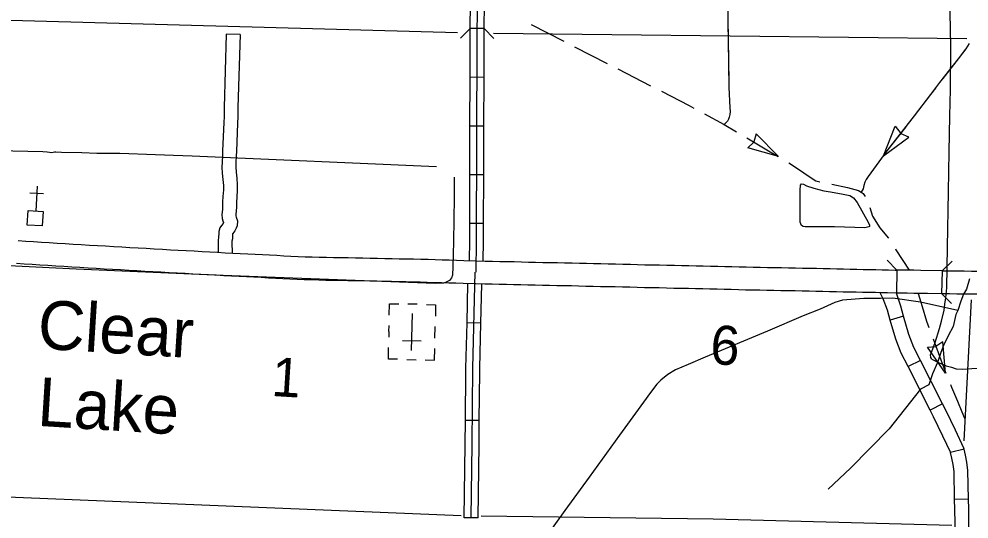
# Model space of a CAD drawing. Extents: x 1366406 to 1373462, y 376856 to 381998.
# Drawn here: x 1369358.5 to 1369525.2, y 379511.9 to 379599.7 of the extents above; entities that cross this region are included whole.
import ezdxf

# ---------------------------------------------------------------- set-up
doc = ezdxf.new("R2010")
doc.units = 0
for name, color, linetype in [('10', 7, 'Continuous'), ('24', 7, 'Continuous'), ('31', 7, 'Continuous'), ('32', 7, 'Continuous'), ('35', 7, 'Continuous'), ('37', 7, 'Continuous'), ('38', 7, 'Continuous'), ('4', 7, 'Continuous'), ('43', 7, 'Continuous'), ('45', 7, 'Continuous'), ('46', 7, 'Continuous'), ('5', 7, 'Continuous'), ('57', 7, 'Continuous')]:
    doc.layers.add(name, color=color, linetype=linetype)

msp = doc.modelspace()

# ---------------------------------------------------------------- linework, layer by layer
at = {"layer": '10'}
msp.add_line((1369520.56, 379555.48), (1369520.53, 379555.48), dxfattribs=at)
for points in [[(1369358.35, 379560.78), (1369359.71, 379560.69), (1369361.07, 379560.6), (1369362.44, 379560.52), (1369363.82, 379560.44), (1369365.22, 379560.35), (1369366.63, 379560.26), (1369368.03, 379560.17), (1369369.45, 379560.08), (1369370.86, 379560), (1369372.28, 379559.92), (1369373.71, 379559.84), (1369375.15, 379559.75), (1369376.57, 379559.66), (1369377.99, 379559.58), (1369379.4, 379559.5), (1369380.82, 379559.43), (1369382.25, 379559.35), (1369383.67, 379559.26), (1369385.08, 379559.18), (1369386.47, 379559.1), (1369387.86, 379559.02), (1369389.25, 379558.95), (1369390.63, 379558.88), (1369391.99, 379558.8), (1369393.37, 379558.73), (1369394.7, 379558.65), (1369396.02, 379558.57), (1369397.33, 379558.51), (1369398.64, 379558.45), (1369399.94, 379558.39), (1369401.22, 379558.32), (1369402.49, 379558.26), (1369403.76, 379558.19), (1369405.01, 379558.13), (1369406.24, 379558.07), (1369407.51, 379558.01), (1369408.72, 379557.95), (1369409.96, 379557.91)], [(1369409.82, 379553.86), (1369408.55, 379553.9), (1369407.31, 379553.96), (1369406.05, 379554.03), (1369404.81, 379554.09), (1369403.56, 379554.15), (1369402.29, 379554.21), (1369401.01, 379554.28), (1369399.74, 379554.34), (1369398.45, 379554.4), (1369397.14, 379554.46), (1369395.81, 379554.53), (1369394.46, 379554.6), (1369393.14, 379554.69), (1369391.78, 379554.76), (1369390.41, 379554.83), (1369389.04, 379554.91), (1369387.65, 379554.98), (1369386.25, 379555.05), (1369384.84, 379555.13), (1369383.43, 379555.22), (1369382.02, 379555.31), (1369380.61, 379555.38), (1369379.19, 379555.46), (1369377.76, 379555.53), (1369376.33, 379555.62), (1369374.9, 379555.71), (1369373.47, 379555.79), (1369372.05, 379555.88), (1369370.63, 379555.96), (1369369.21, 379556.04), (1369367.78, 379556.13), (1369366.37, 379556.22), (1369364.96, 379556.31), (1369363.57, 379556.39), (1369362.19, 379556.48), (1369360.81, 379556.56), (1369359.44, 379556.65), (1369358.08, 379556.74)], [(1369409.95, 379557.91), (1369411.21, 379557.87), (1369412.46, 379557.84), (1369413.72, 379557.82), (1369414.99, 379557.8), (1369416.27, 379557.78), (1369417.56, 379557.76), (1369418.85, 379557.74), (1369420.14, 379557.71), (1369421.42, 379557.68), (1369422.7, 379557.65), (1369423.97, 379557.63), (1369425.24, 379557.6), (1369426.5, 379557.58), (1369427.76, 379557.55), (1369429.02, 379557.52), (1369430.29, 379557.49), (1369431.55, 379557.44), (1369432.78, 379557.4), (1369434.02, 379557.37), (1369435.29, 379557.34), (1369436.57, 379557.31), (1369438.63, 379557.24), (1369438.79, 379557.24), (1369440.34, 379557.19), (1369441.61, 379557.17), (1369442.88, 379557.13), (1369444.14, 379557.1), (1369445.4, 379557.08), (1369446.67, 379557.04), (1369447.94, 379557.01), (1369449.17, 379556.98), (1369450.45, 379556.96), (1369451.7, 379556.93), (1369452.98, 379556.91), (1369454.24, 379556.88), (1369455.57, 379556.87), (1369456.84, 379556.82), (1369458.08, 379556.79), (1369459.35, 379556.76), (1369460.64, 379556.74), (1369461.91, 379556.71), (1369463.21, 379556.68), (1369464.5, 379556.65), (1369465.79, 379556.62), (1369467.07, 379556.59), (1369468.34, 379556.55), (1369469.63, 379556.53), (1369470.93, 379556.51), (1369472.22, 379556.47), (1369473.51, 379556.44), (1369474.78, 379556.41), (1369476.05, 379556.39), (1369477.32, 379556.37), (1369478.59, 379556.34), (1369479.86, 379556.31), (1369481.12, 379556.28), (1369482.37, 379556.25), (1369483.62, 379556.22), (1369484.87, 379556.18), (1369486.11, 379556.15), (1369487.35, 379556.12), (1369488.59, 379556.1), (1369489.83, 379556.08), (1369491.07, 379556.06), (1369492.3, 379556.03), (1369493.54, 379556.01), (1369494.76, 379555.98), (1369495.99, 379555.96), (1369497.22, 379555.94), (1369498.44, 379555.91), (1369499.65, 379555.88), (1369500.84, 379555.85), (1369502.02, 379555.83), (1369503.19, 379555.8), (1369504.35, 379555.78), (1369505.51, 379555.75), (1369506.64, 379555.73), (1369507.75, 379555.7), (1369508.86, 379555.69), (1369509.96, 379555.66), (1369511.06, 379555.63), (1369512.25, 379555.59), (1369512.57, 379555.59)], [(1369512.57, 379555.59), (1369512.5, 379551.54), (1369510.94, 379551.58), (1369509.86, 379551.61), (1369508.78, 379551.64), (1369507.68, 379551.66), (1369506.55, 379551.68), (1369505.42, 379551.7), (1369504.27, 379551.73), (1369503.11, 379551.75), (1369501.94, 379551.78), (1369500.75, 379551.8), (1369499.55, 379551.83), (1369498.34, 379551.86), (1369497.14, 379551.89), (1369495.92, 379551.91), (1369494.69, 379551.94), (1369493.46, 379551.96), (1369492.22, 379551.98), (1369490.99, 379552.01), (1369489.75, 379552.03), (1369488.51, 379552.05), (1369487.27, 379552.08), (1369486.02, 379552.1), (1369484.76, 379552.14), (1369483.51, 379552.17), (1369482.27, 379552.2), (1369481.02, 379552.23), (1369479.76, 379552.26), (1369478.51, 379552.29), (1369477.25, 379552.32), (1369475.98, 379552.34), (1369474.7, 379552.36), (1369473.41, 379552.39), (1369472.13, 379552.43), (1369470.84, 379552.46), (1369469.55, 379552.48), (1369468.25, 379552.51), (1369466.96, 379552.54), (1369465.68, 379552.58), (1369464.4, 379552.61), (1369463.12, 379552.64), (1369461.82, 379552.66), (1369460.55, 379552.69), (1369459.28, 379552.71), (1369457.99, 379552.74), (1369456.7, 379552.77), (1369455.48, 379552.82), (1369454.18, 379552.83), (1369452.89, 379552.86), (1369451.62, 379552.88), (1369450.37, 379552.91), (1369449.1, 379552.93), (1369447.83, 379552.96), (1369446.57, 379552.99), (1369445.31, 379553.03), (1369444.04, 379553.06), (1369442.78, 379553.08), (1369441.53, 379553.12), (1369440.25, 379553.14), (1369438.66, 379553.19), (1369438.49, 379553.19), (1369436.45, 379553.26), (1369435.19, 379553.29), (1369433.94, 379553.32), (1369432.67, 379553.35), (1369431.4, 379553.39), (1369430.16, 379553.44), (1369428.92, 379553.47), (1369427.67, 379553.5), (1369426.42, 379553.53), (1369425.16, 379553.55), (1369423.89, 379553.58), (1369422.62, 379553.6), (1369421.33, 379553.63), (1369420.05, 379553.66), (1369418.77, 379553.69), (1369417.49, 379553.71), (1369416.21, 379553.74), (1369414.94, 379553.75), (1369413.65, 379553.77), (1369412.37, 379553.79), (1369411.1, 379553.82), (1369409.83, 379553.86)], [(1369520.56, 379555.48), (1369516.78, 379555.55), (1369515.56, 379555.57), (1369512.57, 379555.59)], [(1369533.29, 379551.28), (1369532, 379551.3), (1369530.73, 379551.32), (1369529.45, 379551.33), (1369528.18, 379551.35), (1369526.9, 379551.36), (1369525.61, 379551.37), (1369524.33, 379551.39), (1369523.06, 379551.4), (1369521.78, 379551.41), (1369520.49, 379551.43), (1369520.44, 379551.43), (1369520.56, 379555.48)], [(1369520.53, 379555.48), (1369520.56, 379555.48), (1369521.82, 379555.46), (1369523.09, 379555.45), (1369524.38, 379555.44), (1369525.66, 379555.42), (1369526.94, 379555.41), (1369528.22, 379555.4), (1369529.5, 379555.38), (1369530.79, 379555.37), (1369532.07, 379555.35), (1369533.35, 379555.33)], [(1369520.49, 379551.43), (1369517.95, 379551.48), (1369516.7, 379551.5), (1369515.51, 379551.52), (1369514.34, 379551.53), (1369512.5, 379551.54)]]:
    msp.add_lwpolyline(points, dxfattribs=at)
at = {"layer": '31'}
msp.add_lwpolyline([(1369518.7, 379539.94), (1369519.99, 379539.34), (1369521.22, 379538.81), (1369522.12, 379538.54), (1369522.97, 379538.26), (1369524.13, 379538.19), (1369525.72, 379538.32), (1369526.71, 379538.39), (1369527.68, 379538.45), (1369530.55, 379538.61), (1369534.4, 379538.6), (1369563.62, 379538.83), (1369564.22, 379538.94), (1369564.66, 379539.22), (1369564.83, 379539.54), (1369564.88, 379539.85), (1369564.96, 379543.36), (1369565.19, 379558.13), (1369565.46, 379598.16), (1369565.57, 379608.14), (1369565.83, 379631.95), (1369565.94, 379634.8), (1369566.02, 379636.5)], dxfattribs=at)
at = {"layer": '32'}
for p, q in [((1369440.14, 379597.97), (1369437.71, 379597.99)), ((1369440.11, 379589.42), (1369437.68, 379589.43)), ((1369440.08, 379580.87), (1369437.65, 379580.88)), ((1369440.06, 379572.31), (1369437.63, 379572.32)), ((1369440.03, 379563.76), (1369437.6, 379563.77)), ((1369513.73, 379547.52), (1369511.39, 379546.84)), ((1369516.68, 379539.76), (1369514.52, 379538.66)), ((1369520.57, 379532.14), (1369518.4, 379531.04)), ((1369524.35, 379524.15), (1369521.99, 379523.59)), ((1369525.12, 379515.41), (1369522.69, 379515.35))]:
    msp.add_line(p, q, dxfattribs=at)
for points in [[(1369438.72, 379555.21), (1369438.81, 379560.76), (1369438.91, 379595.76), (1369438.95, 379602.35), (1369438.99, 379604.79), (1369439.05, 379606.18), (1369439.14, 379607.55), (1369439.14, 379619.93), (1369439.06, 379625.24)], [(1369437.71, 379597.99), (1369437.74, 379602.37), (1369437.78, 379604.83), (1369437.84, 379606.25), (1369437.86, 379606.61)], [(1369440.14, 379597.97), (1369440.17, 379602.34), (1369440.2, 379604.76), (1369440.26, 379606.11), (1369440.29, 379606.45)], [(1369518.7, 379539.94), (1369518.51, 379540.26), (1369518.48, 379540.74), (1369518.7, 379541.32), (1369519.3, 379542.91), (1369520.05, 379545.34), (1369520.38, 379546.61), (1369520.87, 379548.55), (1369520.98, 379549.59), (1369521.16, 379550.73), (1369521.32, 379552.51), (1369521.42, 379559.65), (1369521.59, 379569.35), (1369521.76, 379576.33), (1369521.84, 379582.62), (1369521.98, 379587.3), (1369522.01, 379595.1), (1369521.97, 379597.66), (1369521.83, 379604.34)], [(1369437.68, 379589.43), (1369437.7, 379595.77), (1369437.71, 379597.99)], [(1369440.11, 379589.42), (1369440.13, 379595.76), (1369440.14, 379597.97)], [(1369437.65, 379580.88), (1369437.68, 379589.43)], [(1369440.08, 379580.87), (1369440.11, 379589.42)], [(1369437.63, 379572.32), (1369437.65, 379580.88)], [(1369440.06, 379572.31), (1369440.08, 379580.87)], [(1369437.6, 379563.77), (1369437.63, 379572.32)], [(1369440.03, 379563.76), (1369440.06, 379572.31)], [(1369437.54, 379557.28), (1369437.6, 379560.77), (1369437.6, 379563.77)], [(1369439.97, 379557.19), (1369440.03, 379560.75), (1369440.03, 379563.76)], [(1369511.39, 379546.84), (1369510.89, 379548.56), (1369510.18, 379550.58), (1369509.62, 379551.62)], [(1369513.73, 379547.52), (1369513.23, 379549.24), (1369512.5, 379551.54)], [(1369514.52, 379538.66), (1369513.32, 379541), (1369512.37, 379543.5), (1369511.39, 379546.84)], [(1369516.68, 379539.76), (1369515.55, 379541.99), (1369514.67, 379544.27), (1369513.73, 379547.52)], [(1369518.4, 379531.04), (1369514.52, 379538.66)], [(1369520.57, 379532.14), (1369516.68, 379539.76)], [(1369524.35, 379524.15), (1369524.31, 379524.35), (1369522.83, 379527.52), (1369521.18, 379530.92), (1369520.57, 379532.14)], [(1369522, 379523.55), (1369520.63, 379526.48), (1369519.01, 379529.85), (1369518.4, 379531.04)], [(1369522.69, 379515.35), (1369522.59, 379520.27), (1369522.43, 379521.5), (1369522.22, 379522.59), (1369521.99, 379523.59)], [(1369525.12, 379515.41), (1369525.01, 379520.45), (1369524.83, 379521.88), (1369524.6, 379523.1), (1369524.35, 379524.15)], [(1369522.75, 379506.83), (1369522.76, 379511.12), (1369522.73, 379513.66), (1369522.69, 379515.35)], [(1369525.18, 379506.82), (1369525.19, 379511.13), (1369525.16, 379513.71), (1369525.12, 379515.41)]]:
    msp.add_lwpolyline(points, dxfattribs=at)
at = {"layer": '35'}
for points in [[(1369501.62, 379563.17), (1369496.48, 379563.2), (1369496.09, 379563.26), (1369495.81, 379563.41), (1369495.58, 379564.01), (1369495.61, 379569.61), (1369495.63, 379570.53), (1369495.81, 379570.75), (1369496.16, 379570.69), (1369496.7, 379570.36), (1369497.99, 379569.96), (1369499.76, 379569.48), (1369500.9, 379569.35)], [(1369500.9, 379569.35), (1369503.13, 379568.94), (1369504.32, 379568.66), (1369504.96, 379568.25), (1369505.59, 379567.45), (1369507.5, 379563.98), (1369507.77, 379563.51), (1369507.75, 379563.25), (1369507.65, 379563.19), (1369506.92, 379563), (1369501.62, 379563.17)]]:
    msp.add_lwpolyline(points, dxfattribs=at)
at = {"layer": '37'}
for points in [[(1369510.88, 379557.34), (1369512.57, 379555.59)], [(1369520.54, 379555.51), (1369522.28, 379557.19)], [(1369512.5, 379551.54), (1369512.5, 379551.54)], [(1369522.16, 379549.71), (1369520.47, 379551.46)]]:
    msp.add_lwpolyline(points, dxfattribs=at)
at = {"layer": '38'}
for points in [[(1369435.98, 379596.28), (1369437.71, 379597.99)], [(1369440.14, 379597.97), (1369441.85, 379596.24)]]:
    msp.add_lwpolyline(points, dxfattribs=at)
at = {"layer": '4'}
for points in [[(1369435.47, 379597.25), (1369354.8, 379599.47), (1369353.11, 379599.52), (1369318.41, 379599.46), (1369311.47, 379599.63)], [(1369524.83, 379596.17), (1369441.79, 379597.12)]]:
    msp.add_lwpolyline(points, dxfattribs=at)
at = {"layer": '43'}
for p, q in [((1369510.2, 379575.67), (1369512.27, 379580.83)), ((1369512.27, 379580.83), (1369513.33, 379579.49)), ((1369487.87, 379579.5), (1369487.47, 379578.08)), ((1369491.76, 379575.52), (1369487.87, 379579.5)), ((1369510.2, 379575.67), (1369514.68, 379578.95)), ((1369514.68, 379578.95), (1369513.33, 379579.49)), ((1369486.41, 379577.03), (1369487.46, 379578.06)), ((1369491.76, 379575.52), (1369486.41, 379577.03)), ((1369517.91, 379542.05), (1369519.38, 379542.18)), ((1369521.1, 379537.5), (1369517.91, 379542.05)), ((1369520.61, 379543.03), (1369519.4, 379542.19)), ((1369521.1, 379537.5), (1369520.61, 379543.03))]:
    msp.add_line(p, q, dxfattribs=at)
for points in [[(1369482.56, 379624.5), (1369483.09, 379587.69), (1369483.23, 379584.06), (1369483.3, 379583.41), (1369483.23, 379582.92), (1369483.13, 379582.46), (1369483.03, 379582.1), (1369482.81, 379581.76), (1369482.24, 379581.17)], [(1369448.4, 379598.71), (1369451.26, 379597.25)], [(1369482.92, 379599.01), (1369483.02, 379592.6)], [(1369451.26, 379597.25), (1369454.11, 379595.78)], [(1369525.24, 379595.36), (1369524.65, 379594.44), (1369523.3, 379592.69), (1369520.05, 379588.51), (1369518.48, 379586.42), (1369515.6, 379582.65), (1369510.82, 379576.51), (1369507.5, 379572.05), (1369507.19, 379571.52), (1369506.91, 379571.01), (1369506.76, 379570.46), (1369506.62, 379569.88), (1369506.32, 379569.29)], [(1369456.01, 379594.8), (1369461.72, 379591.87)], [(1369524.55, 379594.31), (1369523.3, 379592.69), (1369520.61, 379589.24)], [(1369463.62, 379590.89), (1369469.32, 379587.96)], [(1369483.05, 379590.46), (1369483.09, 379587.69), (1369483.23, 379584.06), (1369483.23, 379584.05)], [(1369471.23, 379586.98), (1369476.13, 379584.46), (1369476.92, 379584.04)], [(1369519.32, 379587.54), (1369518.48, 379586.42), (1369515.6, 379582.65), (1369515.43, 379582.44)], [(1369478.81, 379583.02), (1369482.24, 379581.17), (1369484.4, 379579.89)], [(1369482.94, 379581.97), (1369482.81, 379581.76), (1369482.24, 379581.17)], [(1369514.12, 379580.75), (1369510.82, 379576.51), (1369510.2, 379575.67)], [(1369486.24, 379578.8), (1369490.32, 379576.37), (1369491.75, 379575.51)], [(1369431.8, 379573.71), (1369388.88, 379575.58), (1369385.6, 379575.68), (1369382.45, 379575.81), (1369376.21, 379576.06), (1369372.2, 379576.08), (1369369.56, 379576.16), (1369365.95, 379576.24), (1369364.98, 379576.32), (1369364.76, 379576.28), (1369364.25, 379576.19), (1369363.45, 379576.27), (1369362.71, 379576.35), (1369318.1, 379577.32)], [(1369493.58, 379574.4), (1369494.61, 379573.77), (1369496.26, 379572.64)], [(1369508.92, 379573.95), (1369507.5, 379572.05), (1369507.19, 379571.52), (1369506.91, 379571.01), (1369506.76, 379570.46), (1369506.62, 379569.88), (1369506.32, 379569.29)], [(1369434.9, 379571.88), (1369434.9, 379568.36), (1369434.74, 379560.59), (1369434.66, 379556.18), (1369434.58, 379554.72), (1369434.43, 379554.22), (1369434.06, 379553.75), (1369433.35, 379553.41), (1369432.98, 379553.28), (1369431.56, 379553.27), (1369403.46, 379554.28), (1369392.81, 379554.72), (1369368.55, 379555.77), (1369350.77, 379556.66), (1369342.6, 379557.05)], [(1369496.26, 379572.64), (1369497.68, 379571.66), (1369498.32, 379571.25), (1369499.03, 379571.1)], [(1369501.12, 379570.66), (1369503.91, 379570.07), (1369505.83, 379569.56), (1369506.32, 379569.29), (1369506.66, 379569.02), (1369506.97, 379568.53)], [(1369507.79, 379566.57), (1369508.3, 379565.05), (1369509.58, 379563.02), (1369511.08, 379561.23)], [(1369512.32, 379559.3), (1369512.4, 379559.13), (1369514.73, 379555.59)], [(1369525.29, 379554.09), (1369524.76, 379552.27), (1369524.27, 379551.4), (1369523.78, 379550.17), (1369523.24, 379548.49), (1369522.9, 379547.78), (1369522.41, 379545.72), (1369521.55, 379544.08), (1369520.73, 379542.39), (1369520.29, 379541.11), (1369519.67, 379539.38), (1369518.79, 379537.4), (1369518.19, 379535.47), (1369516.73, 379534.68), (1369511.19, 379527.74), (1369504.42, 379520.86), (1369500.49, 379517.18)], [(1369516.3, 379551.5), (1369516.99, 379549.21), (1369517.76, 379546.64), (1369518.17, 379545.53)], [(1369523.24, 379548.49), (1369516.72, 379549.98), (1369511.84, 379550.67), (1369509.69, 379550.61), (1369506.74, 379550.64), (1369503.03, 379550.32), (1369501.69, 379549.92), (1369499.12, 379548.77), (1369496.1, 379547.55), (1369489.87, 379544.86), (1369478.9, 379540.31), (1369475.95, 379539.06), (1369473.71, 379538.11), (1369472.34, 379537.25), (1369471.13, 379536.31), (1369470.46, 379535.57), (1369469.31, 379534.11), (1369468.07, 379532.4), (1369463.89, 379526.63), (1369458.54, 379519.24), (1369454.31, 379513.44), (1369451.03, 379508.82)], [(1369518.9, 379543.52), (1369520.25, 379539.83), (1369521.17, 379537.52)], [(1369521.95, 379535.53), (1369522.14, 379535.05), (1369523.18, 379532.57)], [(1369523.18, 379532.57), (1369523.95, 379530.75), (1369524.42, 379529.61)]]:
    msp.add_lwpolyline(points, dxfattribs=at)
at = {"layer": '45'}
for p, q in [((1369439.57, 379546.29), (1369437.14, 379546.35)), ((1369439.29, 379529.21), (1369436.86, 379529.23)), ((1369439.06, 379512.1), (1369436.63, 379512.13))]:
    msp.add_line(p, q, dxfattribs=at)
for points in [[(1369437.85, 379512.11), (1369438.03, 379525.06), (1369438.17, 379538.39), (1369438.56, 379555.22)], [(1369437.14, 379546.35), (1369437.3, 379553.23)], [(1369439.57, 379546.29), (1369439.73, 379553.15)], [(1369436.95, 379537.78), (1369436.95, 379538.41), (1369437.14, 379546.35)], [(1369439.38, 379537.76), (1369439.38, 379538.37), (1369439.57, 379546.29)], [(1369436.86, 379529.23), (1369436.95, 379537.78)], [(1369439.29, 379529.21), (1369439.38, 379537.76)], [(1369436.75, 379520.68), (1369436.81, 379525.07), (1369436.86, 379529.23)], [(1369439.18, 379520.65), (1369439.24, 379525.04), (1369439.29, 379529.21)], [(1369436.63, 379512.13), (1369436.75, 379520.68)], [(1369439.06, 379512.1), (1369439.18, 379520.65)]]:
    msp.add_lwpolyline(points, dxfattribs=at)
at = {"layer": '46'}
for points in [[(1369397.3, 379596.94), (1369394.88, 379597.01), (1369394.49, 379584.16), (1369394.49, 379582.53), (1369394.46, 379581.47), (1369394.24, 379576.54), (1369394.2, 379575.79), (1369394.14, 379574.56), (1369394.13, 379573.64), (1369394.17, 379572.58), (1369394.29, 379571.52), (1369394.37, 379570.46), (1369394.37, 379569.68), (1369394.3, 379568.54), (1369394.25, 379567.57), (1369394.25, 379566.82), (1369394.2, 379566.22), (1369394.09, 379565.37), (1369394.19, 379564.66), (1369394.31, 379564.23), (1369394.39, 379563.93), (1369394.39, 379563.93), (1369394.32, 379563.79), (1369394.06, 379563.44), (1369393.74, 379562.99), (1369393.58, 379562.37), (1369393.58, 379562.17), (1369393.56, 379561.99), (1369393.52, 379561.42), (1369393.52, 379561.28), (1369393.45, 379560.89), (1369393.45, 379558.72)], [(1369397.3, 379596.94), (1369396.92, 379584.12), (1369396.92, 379582.49), (1369396.88, 379581.38), (1369396.67, 379576.41), (1369396.62, 379575.66), (1369396.57, 379574.49), (1369396.56, 379573.68), (1369396.6, 379572.76), (1369396.71, 379571.75), (1369396.8, 379570.55), (1369396.8, 379569.6), (1369396.72, 379568.4), (1369396.68, 379567.51), (1369396.68, 379566.72), (1369396.62, 379565.96), (1369396.54, 379565.39), (1369396.58, 379565.14), (1369396.65, 379564.88), (1369396.83, 379564.24), (1369396.81, 379563.38), (1369396.62, 379562.94), (1369396.39, 379562.49), (1369396.01, 379562), (1369396, 379561.98), (1369395.98, 379561.79), (1369395.95, 379561.33), (1369395.95, 379561.07), (1369395.88, 379560.68), (1369395.88, 379560.52), (1369395.92, 379558.58)]]:
    msp.add_lwpolyline(points, dxfattribs=at)
at = {"layer": '5'}
for points in [[(1369525.62, 379550.39), (1369524.32, 379525.62)], [(1369436.09, 379512.5), (1369355, 379515.81)], [(1369522.22, 379510.75), (1369480.32, 379511.88), (1369439.59, 379512.42)]]:
    msp.add_lwpolyline(points, dxfattribs=at)
at = {"layer": '57'}
for p, q in [((1369361.71, 379570.31), (1369361.44, 379565.95)), ((1369360.42, 379569.17), (1369362.84, 379569.02)), ((1369428.37, 379549.59), (1369426.75, 379549.62)), ((1369427.41, 379541.51), (1369427.54, 379547.99)), ((1369423.43, 379544.83), (1369423.41, 379543.83)), ((1369423.43, 379544.83), (1369423.45, 379545.85)), ((1369431.5, 379543.67), (1369431.54, 379545.7)), ((1369429.06, 379543.1), (1369425.81, 379543.16)), ((1369427.47, 379544.75), (1369427.47, 379544.75)), ((1369427.47, 379544.75), (1369427.47, 379544.75)), ((1369426.56, 379539.91), (1369428.18, 379539.87))]:
    msp.add_line(p, q, dxfattribs=at)
msp.add_lwpolyline([(1369359.96, 379563.51), (1369360.12, 379566.04), (1369362.74, 379565.87), (1369362.58, 379563.35)], close=True, dxfattribs=at)
for points in [[(1369423.48, 379547.66), (1369423.52, 379549.69), (1369425.14, 379549.65)], [(1369430, 379549.56), (1369431.62, 379549.53), (1369431.58, 379547.5)], [(1369424.95, 379539.94), (1369423.33, 379539.97), (1369423.37, 379541.99)], [(1369429.81, 379539.84), (1369431.43, 379539.81), (1369431.47, 379541.83)]]:
    msp.add_lwpolyline(points, dxfattribs=at)

# ---------------------------------------------------------------- texts
at = {"layer": '24'}
for s, p in [('Clear', (1369361.62, 379541.86)), ('Lake', (1369361.59, 379528.28))]:
    msp.add_text(s, height=8.554, rotation=356.4139, dxfattribs=at).set_placement(p)
at = {"layer": '5'}
for s, p in [('6', (1369479.68, 379539.15)), ('1', (1369402.69, 379533.53))]:
    msp.add_text(s, height=6.84, rotation=356.4139, dxfattribs=at).set_placement(p)

doc.saveas('drawing.dxf')
